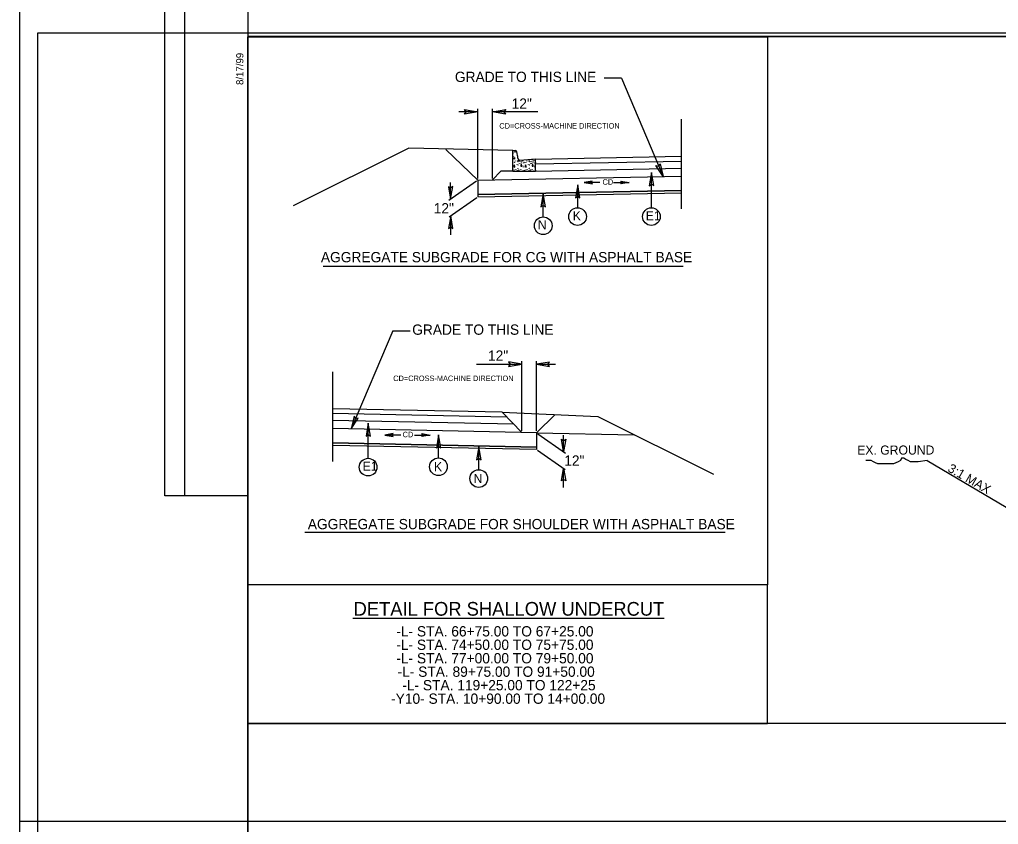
# Model space of a CAD drawing. Extents: x 2320980 to 2456309, y 595047 to 606177.
# Drawn here: x 2455708.8 to 2455851.6, y 597279.1 to 597396.6 of the extents above; entities that cross this region are included whole.
import ezdxf

# ---------------------------------------------------------------- set-up
doc = ezdxf.new("R2010")
doc.units = 0
for name, color, linetype in [('Old_Level_1', 7, 'Continuous'), ('Old_Level_11', 7, 'Continuous'), ('Old_Level_20', 7, 'Continuous'), ('Old_Level_21', 7, 'Continuous'), ('Old_Level_4', 7, 'Continuous'), ('Prop Dimension', 7, 'Continuous'), ('Prop Dimension Text', 7, 'Continuous'), ('Prop Terminator CELL', 7, 'Continuous'), ('Sheet Block Revision CELL', 7, 'Continuous'), ('Sheet Cutting Line CELL', 7, 'Continuous'), ('Sheet Plan CELL', 7, 'Continuous'), ('Sheet Plot Border Inside CELL', 7, 'Continuous'), ('Sheet Plot Border Outside CELL', 7, 'Continuous'), ('Typical Curb CELL', 7, 'Continuous'), ('Typical Hinge Slope Arterial CELL', 7, 'Continuous'), ('Typical Hinge Slope Interstate CELL', 7, 'Continuous'), ('Typical ID Circle CELL', 7, 'Continuous'), ('Typical Pavement Slope CELL', 7, 'Continuous'), ('Typical Shoulder Slope CELL', 7, 'Continuous'), ('Typical Terminator CELL', 7, 'Continuous'), ('Typical Text General CELL', 7, 'Continuous')]:
    doc.layers.add(name, color=color, linetype=linetype)

msp = doc.modelspace()

# ---------------------------------------------------------------- linework, layer by layer
at = {"layer": 'Old_Level_11'}
for points in [[(2455742.1, 597293.82), (2455817.91, 597293.82), (2455817.91, 597314.05), (2455742.1, 597314.05)], [(2455742.1, 597184.08), (2455863.37, 597184.08), (2455863.37, 597293.82), (2455742.1, 597293.82)]]:
    msp.add_lwpolyline(points, close=True, dxfattribs=at)
at = {"layer": 'Old_Level_21'}
msp.add_line((2455841.24, 597332.21), (2455856.03, 597323.45), dxfattribs=at)
at = {"layer": 'Old_Level_4'}
msp.add_lwpolyline([(2455742.1, 597394.07), (2455817.91, 597394.07), (2455817.91, 597314.05), (2455742.1, 597314.05)], close=True, dxfattribs=at)
at = {"layer": 'Prop Dimension'}
for p, q in [((2455796.63, 597388.02), (2455794.08, 597388.02)), ((2455796.63, 597388.02), (2455802.71, 597373.67)), ((2455805.38, 597368.93), (2455805.38, 597382.02)), ((2455793.45, 597372.79), (2455791.16, 597372.79)), ((2455795.46, 597372.79), (2455797.75, 597372.79)), ((2455753.09, 597360.59), (2455805.61, 597360.59)), ((2455763.24, 597351.16), (2455757.16, 597336.82)), ((2455763.24, 597351.16), (2455765.79, 597351.16)), ((2455754.49, 597332.07), (2455754.49, 597345.16)), ((2455764.41, 597335.94), (2455762.12, 597335.94)), ((2455766.42, 597335.94), (2455768.71, 597335.94)), ((2455750.42, 597321.77), (2455811.73, 597321.77)), ((2455757.41, 597309.22), (2455802.86, 597309.22))]:
    msp.add_line(p, q, dxfattribs=at)
at = {"layer": 'Prop Dimension Text'}
for p, q in [((2455775.66, 597373.39), (2455775.66, 597383.55)), ((2455777.8, 597373.39), (2455777.8, 597383.55)), ((2455775.66, 597383.12), (2455772.89, 597383.12)), ((2455784.41, 597383.12), (2455777.8, 597383.12)), ((2455775.45, 597372.99), (2455771.41, 597370.16)), ((2455771.7, 597370.36), (2455771.7, 597372.8)), ((2455775.5, 597370.57), (2455771.48, 597367.75)), ((2455771.71, 597365.16), (2455771.71, 597367.92)), ((2455782.07, 597336.53), (2455782.07, 597346.7)), ((2455784.21, 597336.53), (2455784.21, 597346.7)), ((2455775.46, 597346.26), (2455782.07, 597346.26)), ((2455784.21, 597346.26), (2455786.98, 597346.26)), ((2455784.42, 597336.13), (2455788.45, 597333.31)), ((2455788.17, 597333.51), (2455788.17, 597335.94)), ((2455784.37, 597333.72), (2455788.39, 597330.9)), ((2455788.16, 597328.3), (2455788.16, 597331.06))]:
    msp.add_line(p, q, dxfattribs=at)
for centre in [(2455785.2, 597366.49), (2455790.21, 597367.81), (2455800.98, 597367.81), (2455759.66, 597331.25), (2455769.92, 597331.31), (2455775.8, 597329.59)]:
    msp.add_circle(centre, 1.29, dxfattribs=at)
at = {"layer": 'Prop Terminator CELL'}
for points in [[(2455771.39, 597372.18), (2455771.7, 597370.36), (2455772.02, 597372.19), (2455771.7, 597371.95)], [(2455792.36, 597373), (2455791.16, 597372.79), (2455792.37, 597372.58), (2455792.22, 597372.79)], [(2455796.54, 597373), (2455797.75, 597372.79), (2455796.54, 597372.58), (2455796.69, 597372.79)], [(2455772.02, 597366.1), (2455771.71, 597367.92), (2455771.39, 597366.09), (2455771.71, 597366.33)], [(2455763.33, 597336.15), (2455762.12, 597335.94), (2455763.33, 597335.72), (2455763.18, 597335.94)], [(2455767.51, 597336.15), (2455768.71, 597335.94), (2455767.5, 597335.72), (2455767.65, 597335.94)], [(2455788.48, 597335.32), (2455788.17, 597333.51), (2455787.85, 597335.33), (2455788.17, 597335.1)], [(2455787.85, 597329.25), (2455788.16, 597331.06), (2455788.48, 597329.24), (2455788.16, 597329.47)]]:
    msp.add_lwpolyline(points, close=True, dxfattribs=at)
at = {"layer": 'Sheet Block Revision CELL'}
msp.add_line((2455732.91, 597327.08), (2455732.91, 597485.2), dxfattribs=at)
msp.add_lwpolyline([(2455730, 597327.07), (2455730, 597485.2), (2455742.11, 597485.21), (2455742.11, 597327.08)], close=True, dxfattribs=at)
at = {"layer": 'Sheet Cutting Line CELL'}
for p, q in [((2455708.81, 597498.57), (2455708.81, 597279.57)), ((2455708.81, 597279.57), (2456045.51, 597279.57))]:
    msp.add_line(p, q, dxfattribs=at)
at = {"layer": 'Sheet Plan CELL'}
msp.add_line((2455742.1, 597394.08), (2455742.1, 597394.08), dxfattribs=at)
for points in [[(2456042.11, 597394.08), (2455742.1, 597394.08), (2455742.1, 597184.08), (2456042.11, 597184.08)], [(2455742.1, 597184.08), (2455742.1, 597394.07), (2456002.1, 597394.08), (2456002.1, 597364.07), (2456042.11, 597364.06), (2456042.11, 597184.08)]]:
    msp.add_lwpolyline(points, close=True, dxfattribs=at)
at = {"layer": 'Sheet Plot Border Inside CELL'}
msp.add_lwpolyline([(2455711.41, 597183.57), (2456044.6, 597183.58), (2456044.61, 597394.57), (2455711.41, 597394.57)], close=True, dxfattribs=at)
at = {"layer": 'Sheet Plot Border Outside CELL'}
msp.add_lwpolyline([(2455708.81, 597179.57), (2456045.51, 597179.57), (2456045.51, 597398.57), (2455708.81, 597398.57)], close=True, dxfattribs=at)
at = {"layer": 'Typical Curb CELL'}
for p, q in [((2455780.78, 597374.46), (2455780.78, 597377.45)), ((2455780.78, 597377.45), (2455781.13, 597377.45)), ((2455780.83, 597376.32), (2455781.03, 597376.46)), ((2455781.01, 597376.19), (2455780.83, 597376.32)), ((2455781.03, 597376.46), (2455781.01, 597376.19)), ((2455781.44, 597376.71), (2455781.44, 597376.74)), ((2455781, 597375.37), (2455780.86, 597375.14)), ((2455780.86, 597375.14), (2455781.08, 597375.03)), ((2455781.08, 597375.03), (2455781, 597375.37)), ((2455784.1, 597376.21), (2455781.78, 597375.99)), ((2455781.98, 597375.54), (2455781.94, 597375.2)), ((2455781.94, 597375.2), (2455782.1, 597375.18)), ((2455782.1, 597375.18), (2455781.98, 597375.54)), ((2455782.66, 597375.37), (2455782.52, 597375.14)), ((2455782.52, 597375.14), (2455782.74, 597375.03)), ((2455782.74, 597375.03), (2455782.66, 597375.37)), ((2455783.64, 597375.54), (2455783.6, 597375.2)), ((2455783.6, 597375.2), (2455783.76, 597375.18)), ((2455783.76, 597375.18), (2455783.64, 597375.54)), ((2455784.1, 597374.46), (2455784.1, 597376.21)), ((2455780.78, 597374.46), (2455784.1, 597374.46))]:
    msp.add_line(p, q, dxfattribs=at)
for centre in [(2455780.8, 597377.12), (2455780.87, 597376.58), (2455781.09, 597377.23), (2455780.99, 597375.76), (2455781.15, 597375.91), (2455781.39, 597375.42), (2455781.5, 597376), (2455781.51, 597374.87), (2455781.52, 597375.85), (2455781.56, 597375.33), (2455781.75, 597375.59), (2455781.79, 597375.89), (2455782.05, 597375.78), (2455782.18, 597375.91), (2455782.22, 597375.18), (2455782.32, 597375.66), (2455782.34, 597375.04), (2455782.4, 597375.76), (2455782.42, 597375.47), (2455782.66, 597375.76), (2455782.82, 597375.91), (2455783.05, 597375.42), (2455783.16, 597376), (2455783.17, 597374.87), (2455783.18, 597375.85), (2455783.22, 597375.33), (2455783.42, 597375.59), (2455783.45, 597375.89), (2455783.65, 597376.08), (2455783.71, 597375.78), (2455783.84, 597376.03), (2455783.88, 597375.18), (2455783.98, 597375.66), (2455784.01, 597375.04), (2455784.06, 597375.76), (2455784.08, 597375.47), (2455780.97, 597374.6), (2455781.2, 597374.72), (2455781.43, 597374.53), (2455781.66, 597374.62), (2455781.94, 597374.68), (2455782.15, 597374.48), (2455782.43, 597374.55), (2455782.63, 597374.6), (2455782.86, 597374.72), (2455783.1, 597374.53), (2455783.32, 597374.62), (2455783.6, 597374.68), (2455783.81, 597374.48), (2455784.09, 597374.55)]:
    msp.add_ellipse(centre, major_axis=(0, 0.024), ratio=0.444444, dxfattribs=at)
for centre, major_axis, end_param in [((2455781.13, 597376.74), (0, 0.717), 6.283185), ((2455781.76, 597376.71), (0, -0.717), 6.324802)]:
    msp.add_ellipse(centre, major_axis=major_axis, ratio=0.444444, start_param=4.712389, end_param=end_param, dxfattribs=at)
at = {"layer": 'Typical Hinge Slope Arterial CELL'}
msp.add_lwpolyline([(2455841.24, 597332.21), (2455839.93, 597332.04), (2455839.6, 597332.04), (2455839.11, 597332.04), (2455838.78, 597332.04), (2455838.45, 597332.21), (2455838.13, 597332.37), (2455837.8, 597332.54), (2455837.47, 597332.54), (2455837.31, 597332.21), (2455836.98, 597332.04), (2455836.65, 597331.88), (2455836.32, 597331.72), (2455836, 597331.72), (2455835.67, 597331.72), (2455835.34, 597331.72), (2455835.01, 597331.72), (2455834.69, 597331.72), (2455834.36, 597331.72), (2455834.03, 597331.72), (2455833.7, 597331.88), (2455833.37, 597332.04), (2455833.05, 597332.21), (2455832.56, 597332.21), (2455832.28, 597332.21)], dxfattribs=at)
at = {"layer": 'Typical Hinge Slope Interstate CELL'}
for p, q in [((2455765.6, 597377.82), (2455748.74, 597369.39)), ((2455793.17, 597338.64), (2455810.03, 597330.21))]:
    msp.add_line(p, q, dxfattribs=at)
for points in [[(2455805.37, 597371.64), (2455775.65, 597371.05), (2455775.66, 597370.68), (2455805.38, 597371.27)], [(2455754.5, 597334.79), (2455784.22, 597334.19), (2455784.21, 597333.82), (2455754.49, 597334.42)]]:
    msp.add_lwpolyline(points, close=True, dxfattribs=at)
at = {"layer": 'Typical ID Circle CELL'}
for p, q in [((2455801, 597369.1), (2455801, 597374.24)), ((2455790.24, 597369.11), (2455790.24, 597372.44)), ((2455785.22, 597367.78), (2455785.22, 597371.12)), ((2455759.68, 597332.55), (2455759.68, 597337.68)), ((2455769.95, 597332.61), (2455769.95, 597335.95)), ((2455775.82, 597330.89), (2455775.82, 597334.22))]:
    msp.add_line(p, q, dxfattribs=at)
at = {"layer": 'Typical Pavement Slope CELL'}
for p, q in [((2455784.1, 597376.21), (2455805.38, 597376.63)), ((2455784.1, 597375.5), (2455805.39, 597375.92)), ((2455784.1, 597374.47), (2455805.41, 597374.89)), ((2455775.66, 597373.13), (2455805.38, 597373.73)), ((2455775.65, 597371.05), (2455805.37, 597371.64)), ((2455779.22, 597339.28), (2455754.49, 597339.78)), ((2455780.92, 597337.51), (2455754.46, 597338.04)), ((2455779.91, 597338.56), (2455754.48, 597339.07)), ((2455784.21, 597336.28), (2455754.49, 597336.87)), ((2455784.22, 597334.19), (2455754.5, 597334.79))]:
    msp.add_line(p, q, dxfattribs=at)
at = {"layer": 'Typical Shoulder Slope CELL'}
for p, q in [((2455780.78, 597377.45), (2455765.6, 597377.82)), ((2455771.01, 597377.59), (2455775.66, 597373.13)), ((2455777.8, 597373.18), (2455779.04, 597374.46)), ((2455780.78, 597374.46), (2455779.04, 597374.46)), ((2455775.66, 597373.13), (2455775.66, 597371.05)), ((2455775.66, 597370.68), (2455805.38, 597371.27)), ((2455779.22, 597339.28), (2455793.17, 597338.64)), ((2455782.07, 597336.32), (2455779.22, 597339.28)), ((2455786.97, 597338.93), (2455784.21, 597336.28)), ((2455784.21, 597336.28), (2455784.21, 597334.19)), ((2455784.21, 597336.28), (2455798.47, 597335.99)), ((2455784.21, 597333.82), (2455754.49, 597334.42))]:
    msp.add_line(p, q, dxfattribs=at)
at = {"layer": 'Typical Terminator CELL'}
for points in [[(2455779.72, 597382.79), (2455777.8, 597383.12), (2455779.73, 597383.46), (2455779.48, 597383.12)], [(2455773.74, 597383.45), (2455775.66, 597383.12), (2455773.73, 597382.78), (2455773.98, 597383.12)], [(2455802.26, 597375.53), (2455802.71, 597373.67), (2455801.65, 597375.28), (2455802.05, 597375.19)], [(2455801.33, 597372.34), (2455801, 597374.24), (2455800.67, 597372.33), (2455801, 597372.57)], [(2455790.56, 597370.55), (2455790.24, 597372.44), (2455789.9, 597370.54), (2455790.24, 597370.78)], [(2455785.55, 597369.23), (2455785.22, 597371.12), (2455784.88, 597369.22), (2455785.22, 597369.46)], [(2455780.15, 597345.93), (2455782.07, 597346.26), (2455780.14, 597346.6), (2455780.39, 597346.26)], [(2455786.13, 597346.59), (2455784.21, 597346.26), (2455786.14, 597345.92), (2455785.89, 597346.26)], [(2455757.61, 597338.67), (2455757.16, 597336.82), (2455758.22, 597338.42), (2455757.82, 597338.33)], [(2455760.01, 597335.79), (2455759.68, 597337.68), (2455759.35, 597335.78), (2455759.68, 597336.02)], [(2455770.27, 597334.05), (2455769.95, 597335.95), (2455769.61, 597334.04), (2455769.95, 597334.29)], [(2455776.15, 597332.33), (2455775.82, 597334.22), (2455775.49, 597332.32), (2455775.82, 597332.56)]]:
    msp.add_lwpolyline(points, close=True, dxfattribs=at)

# ---------------------------------------------------------------- texts
at = {"layer": 'Old_Level_1'}
msp.add_text('EX. GROUND', height=1.33, rotation=0.0897, dxfattribs=at).set_placement((2455831.01, 597333.07))
at = {"layer": 'Old_Level_20'}
for s, p in [('K', (2455789.51, 597367.28)), ('E1', (2455800.17, 597367.28)), ('N', (2455784.41, 597365.96)), ('E1', (2455758.85, 597330.73)), ('K', (2455769.26, 597330.65)), ('N', (2455775.05, 597328.92))]:
    msp.add_text(s, height=1.33, dxfattribs=at).set_placement(p)
at = {"layer": 'Old_Level_21'}
for s, height, rotation, p in [('3:1 MAX', 1.33, 329.8879, (2455844.11, 597330.7)), ('DETAIL FOR SHALLOW UNDERCUT', 2, 360, (2455757.54, 597309.57))]:
    msp.add_text(s, height=height, rotation=rotation, dxfattribs=at).set_placement(p)
at = {"layer": 'Prop Dimension Text'}
for p in [(2455780.6, 597383.56), (2455769.23, 597368.28), (2455777.15, 597346.78), (2455788.27, 597331.46)]:
    msp.add_text('12"', height=1.5, dxfattribs=at).set_placement(p)
at = {"layer": 'Sheet Plan CELL'}
msp.add_text('8/17/99', height=1.05, rotation=90, dxfattribs=at).set_placement((2455741.46, 597387.03))
at = {"layer": 'Typical Hinge Slope Interstate CELL'}
for s, height, p in [('CD=CROSS-MACHINE DIRECTION', 0.8052, (2455778.8, 597380.66)), ('CD', 0.805, (2455793.86, 597372.47)), ('CD=CROSS-MACHINE DIRECTION', 0.8052, (2455763.32, 597343.81)), ('CD', 0.805, (2455764.69, 597335.61))]:
    msp.add_text(s, height=height, dxfattribs=at).set_placement(p)
at = {"layer": 'Typical Text General CELL'}
for s, p in [('GRADE TO THIS LINE', (2455772.32, 597387.46)), ('AGGREGATE SUBGRADE FOR CG WITH ASPHALT BASE', (2455752.77, 597361.15)), ('GRADE TO THIS LINE', (2455766.09, 597350.57)), ('AGGREGATE SUBGRADE FOR SHOULDER WITH ASPHALT BASE', (2455750.86, 597322.19)), ('-L- STA. 66+75.00 TO 67+25.00', (2455763.77, 597306.54)), ('-L- STA. 74+50.00 TO 75+75.00', (2455763.77, 597304.58)), ('-L- STA. 77+00.00 TO 79+50.00', (2455763.77, 597302.61)), ('-L- STA. 89+75.00 TO 91+50.00', (2455763.95, 597300.65)), ('-L- STA. 119+25.00 TO 122+25', (2455764.64, 597298.68)), ('-Y10- STA. 10+90.00 TO 14+00.00', (2455763.01, 597296.71))]:
    msp.add_text(s, height=1.5, dxfattribs=at).set_placement(p)

doc.saveas('drawing.dxf')
